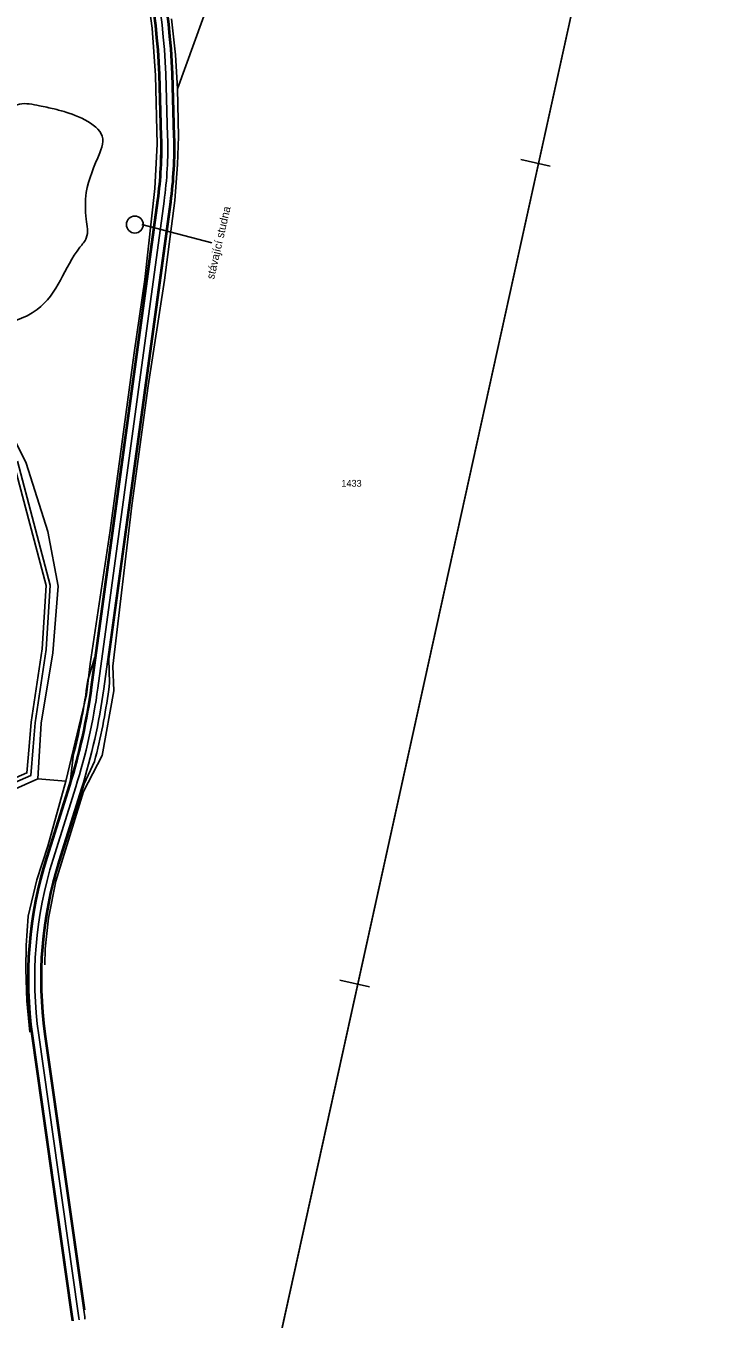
# Model space of a CAD drawing. Extents: x -551035 to -550565, y -1149613 to -1148728.
# Drawn here: x -550737.7 to -550564.5, y -1149286.2 to -1148963 of the extents above; entities that cross this region are included whole.
import ezdxf

# ---------------------------------------------------------------- set-up
doc = ezdxf.new("R2010")
doc.units = 0
for name, color, linetype in [('Implicitní', 7, 'Continuous'), ('u_popis', 7, 'Continuous'), ('u_tune', 7, 'Continuous'), ('u_VC7', 7, 'Continuous'), ('u_vysadba kere', 7, 'Continuous'), ('Vrstva 1', 7, 'Continuous'), ('Vrstva 2', 7, 'Continuous'), ('x_format', 7, 'Continuous')]:
    doc.layers.add(name, color=color, linetype=linetype)

msp = doc.modelspace()

# ---------------------------------------------------------------- linework, layer by layer
at = {"layer": 'Implicitní'}
for p, q in [((-550745.15, -1149612.66), (-550564.52, -1148792.31)), ((-550729.47, -1149171.67), (-550723.8, -1149153.61))]:
    msp.add_line(p, q, dxfattribs=at)
at = {"layer": 'u_popis'}
msp.add_line((-550708.71, -1149012.64), (-550691.21, -1149017.21), dxfattribs=at)
at = {"layer": 'u_tune'}
msp.add_circle((-550710.48, -1149012.66), 2.12, dxfattribs=at)
msp.add_spline([(-550755.26, -1149010.77), (-550751.91, -1148999.83), (-550747.39, -1148988.79), (-550743.7, -1148985.14), (-550739.31, -1148982.57), (-550734.31, -1148982.97), (-550730.66, -1148983.77), (-550727.73, -1148984.56), (-550718.44, -1148991.92), (-550719.24, -1148994.73), (-550722.6, -1149004.65), (-550722.6, -1149011.35), (-550722.6, -1149016.02), (-550724.2, -1149018.35), (-550734.91, -1149033.91), (-550756.49, -1149035.13), (-550756.28, -1149014.27), (-550755.3, -1149010.88)], degree=3, dxfattribs=at)
at = {"layer": 'u_VC7'}
for p, q in [((-550704.03, -1148990.65), (-550704.37, -1148978.21)), ((-550703.78, -1148990.64), (-550704.12, -1148978.2)), ((-550700.78, -1148990.56), (-550701.12, -1148978.12)), ((-550700.54, -1148990.6), (-550700.88, -1148978.15)), ((-550721.45, -1149128.24), (-550704.89, -1149006.57)), ((-550721.2, -1149128.27), (-550704.65, -1149006.61)), ((-550718.23, -1149128.68), (-550701.67, -1149007.01)), ((-550716.96, -1149121.19), (-550701.43, -1149007.05)), ((-550722.23, -1149126.52), (-550720.44, -1149120.8)), ((-550716.96, -1149121.19), (-550716.78, -1149127.27)), ((-550722.44, -1149128.1), (-550722.23, -1149126.52)), ((-550716.99, -1149128.85), (-550716.78, -1149127.27)), ((-550725.88, -1149145.48), (-550726.53, -1149151.44)), ((-550723.16, -1149152.4), (-550720.56, -1149146.88)), ((-550732.57, -1149170.7), (-550726.9, -1149152.64)), ((-550732.33, -1149170.77), (-550726.66, -1149152.72)), ((-550729.47, -1149171.67), (-550723.8, -1149153.61)), ((-550729.23, -1149171.74), (-550723.16, -1149152.4)), ((-550726.46, -1149284.38), (-550736.23, -1149215.44)), ((-550726.22, -1149284.35), (-550735.98, -1149215.4)), ((-550723.25, -1149283.93), (-550733.01, -1149214.98)), ((-550723, -1149283.89), (-550732.76, -1149214.94))]:
    msp.add_line(p, q, dxfattribs=at)
for points in [[(-550702.28, -1148990.6), (-550702.62, -1148978.16)], [(-550719.72, -1149128.48), (-550703.16, -1149006.81)], [(-550730.9, -1149171.22), (-550725.23, -1149153.17)], [(-550724.73, -1149284.14), (-550734.5, -1149215.19)]]:
    msp.add_lwpolyline(points, dxfattribs=at)
for centre, radius, start, end in [((-550887.55, -1148983.2), 183.25, 1.56, 32.073), ((-550887.55, -1148983.2), 183.5, 1.56, 32.073), ((-550887.55, -1148983.2), 185, 1.56, 32.073), ((-550887.55, -1148983.2), 186.5, 1.56, 32.073), ((-550887.55, -1148983.2), 186.75, 1.56, 32.073), ((-550802.25, -1148993.33), 98.25, 352.2503, 1.56), ((-550802.25, -1148993.33), 98.5, 352.2503, 1.56), ((-550802.25, -1148993.33), 100, 352.2503, 1.56), ((-550802.25, -1148993.33), 101.5, 352.2503, 1.56), ((-550802, -1148993.36), 101.5, 352.2503, 1.56), ((-550868.35, -1149108.25), 148.25, 342.5757, 352.2503), ((-550868.35, -1149108.25), 148.5, 342.5757, 352.2503), ((-550868.35, -1149108.25), 147.25, 345.3528, 352.2503), ((-550868.35, -1149108.25), 150, 342.5757, 352.2503), ((-550868.35, -1149108.25), 151.5, 342.5757, 352.2503), ((-550868.35, -1149108.25), 152.75, 345.3513, 352.2503), ((-550635.49, -1149201.17), 101.75, 162.5757, 188.062), ((-550635.49, -1149201.17), 101.5, 162.5757, 188.062), ((-550635.49, -1149201.17), 100, 162.5757, 188.062), ((-550635.49, -1149201.17), 98.5, 162.5757, 188.062), ((-550635.49, -1149201.17), 98.5, 162.5757, 188.062), ((-550635.49, -1149201.17), 98.25, 162.5757, 188.062), ((-550922.75, -1149312.19), 200, 7.4126, 8.062), ((-550922.75, -1149312.19), 201.5, 7.4126, 8.062), ((-550922.75, -1149312.19), 198.25, 7.4126, 8.062), ((-550922.75, -1149312.19), 198.5, 7.4126, 8.062)]:
    msp.add_arc(centre, radius, start, end, dxfattribs=at)
msp.add_ellipse((-550728.18, -1148978.92), major_axis=(0, 28.25), ratio=0.966989, start_param=4.739615, end_param=4.741818, dxfattribs=at)
at = {"layer": 'u_vysadba kere'}
for points in [[(-550740.77, -1149072.07), (-550732.62, -1149102.86), (-550733.61, -1149118.7), (-550736.4, -1149137.02), (-550736.91, -1149143.06), (-550737.44, -1149149.69), (-550795.02, -1149174.85), (-550801.2, -1149177.61), (-550803.58, -1149178.45)], [(-550739.8, -1149071.82), (-550731.62, -1149102.76), (-550732.61, -1149118.81), (-550735.4, -1149137.14), (-550735.91, -1149143.14), (-550736.49, -1149150.37), (-550794.61, -1149175.76), (-550800.83, -1149178.54), (-550803.42, -1149179.45)]]:
    msp.add_lwpolyline(points, dxfattribs=at)
at = {"layer": 'Vrstva 1'}
for p, q in [((-550706.17, -1148963.58), (-550708.03, -1148950.04)), ((-550699.82, -1148978.71), (-550689.61, -1148950.48)), ((-550706.17, -1148963.58), (-550705.34, -1148975.39)), ((-550700.34, -1148970.26), (-550701.3, -1148961.21)), ((-550699.82, -1148978.71), (-550700.34, -1148970.26)), ((-550705.34, -1148975.39), (-550704.9, -1148992.61)), ((-550699.82, -1148978.71), (-550699.61, -1148990.68)), ((-550705.51, -1149003.68), (-550704.9, -1148992.61)), ((-550699.61, -1148990.68), (-550699.84, -1148997.67)), ((-550700.51, -1149006.65), (-550699.84, -1148997.67)), ((-550708.01, -1149026.4), (-550705.51, -1149003.68)), ((-550700.51, -1149006.65), (-550703.06, -1149026.54)), ((-550710.61, -1149044.72), (-550708.01, -1149026.4)), ((-550707.15, -1149052.97), (-550703.06, -1149026.54)), ((-550710.61, -1149044.72), (-550716.61, -1149089.08)), ((-550711.26, -1149082.9), (-550707.15, -1149052.97)), ((-550743.26, -1149060.91), (-550737.61, -1149072.31)), ((-550732.23, -1149089.39), (-550737.61, -1149072.31)), ((-550711.26, -1149082.9), (-550715.95, -1149122.99)), ((-550732.23, -1149089.39), (-550729.6, -1149103.03)), ((-550721.63, -1149122.47), (-550716.61, -1149089.08)), ((-550730.98, -1149119.67), (-550729.6, -1149103.03)), ((-550733.85, -1149137.23), (-550730.98, -1149119.67)), ((-550722.53, -1149130.17), (-550721.63, -1149122.47)), ((-550715.74, -1149129.2), (-550715.95, -1149122.99)), ((-550722.53, -1149130.17), (-550727.68, -1149151.73)), ((-550718.68, -1149145.35), (-550715.74, -1149129.2)), ((-550734.69, -1149151.21), (-550733.85, -1149137.23)), ((-550723.32, -1149154.35), (-550718.68, -1149145.35)), ((-550804.1, -1149181.57), (-550734.69, -1149151.21)), ((-550734.69, -1149151.21), (-550727.68, -1149151.73)), ((-550732.19, -1149167.98), (-550727.68, -1149151.73)), ((-550723.32, -1149154.35), (-550726.42, -1149164.32)), ((-550726.42, -1149164.32), (-550730.19, -1149176.74)), ((-550734.97, -1149176.43), (-550732.19, -1149167.98)), ((-550737.11, -1149185.49), (-550734.97, -1149176.43)), ((-550732.07, -1149186.03), (-550730.19, -1149176.74)), ((-550737.59, -1149192.78), (-550737.11, -1149185.49)), ((-550732.86, -1149193.69), (-550732.07, -1149186.03)), ((-550737.59, -1149192.78), (-550737.69, -1149198.7)), ((-550732.86, -1149193.69), (-550732.99, -1149197.63)), ((-550737.69, -1149198.7), (-550737.47, -1149206.65)), ((-550736.71, -1149214.49), (-550737.47, -1149206.65))]:
    msp.add_line(p, q, dxfattribs=at)
at = {"layer": 'x_format'}
for p, q in [((-550614.07, -1148996.43), (-550606.74, -1148998.05)), ((-550659.23, -1149201.52), (-550651.9, -1149203.13))]:
    msp.add_line(p, q, dxfattribs=at)
msp.add_lwpolyline([(-550564.52, -1148792.31), (-550745.15, -1149612.66), (-551035.2, -1149548.79), (-550854.57, -1148728.45)], close=True, dxfattribs=at)

# ---------------------------------------------------------------- texts
at = {"layer": 'u_popis'}
msp.add_text('stávající studna', height=2, rotation=76.9951, dxfattribs=at).set_placement((-550690.7, -1149026.47))
at = {"layer": 'Vrstva 2'}
msp.add_text('1433', height=1.7, dxfattribs=at).set_placement((-550658.88, -1149078.17))

doc.saveas('drawing.dxf')
